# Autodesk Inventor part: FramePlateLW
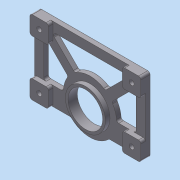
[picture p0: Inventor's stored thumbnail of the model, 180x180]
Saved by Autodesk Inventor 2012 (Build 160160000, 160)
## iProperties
Created: 2010-12
Part Number: FramePlateLW
Document SubType Name: Modeling
Designer: Alex
Density: 2.71 g/cm^3
Material: Aluminum-6061
Mass: 211.967 g
Surface Area: 316.378 cm^2
Volume: 78.2166 cm^3
Author: Alex
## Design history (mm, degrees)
sketch "Sketch1"
  geometry: L1 (-76.2, 76.2)-(76.2, 76.2); L2 (76.2, 76.2)-(76.2, -38.1); L3 (76.2, -38.1)-(-76.2, -38.1); L4 (-76.2, -38.1)-(-76.2, 76.2); C1 r 23.812 at (0, 0); C2 r 28.575 at (0, 0); 1 further point
  constraints: 8 end point, 2 centre point, 2 parallel, 1 horizontal, 1 perpendicular
  dimensions: "d0" = 114.3 distance between parallel lines of L3 L1; "d1" = 152.4 distance between parallel lines of L2 L4; "d2" = 76.2 distance from line of L1 point (0, 0); "d3" = 76.2 distance from line of L4 point (0, 0); "d49" = 47.625 diameter of C1; "d50" = 57.15 diameter of C2
extrude "Extrusion1" new body sketch "Sketch1" distance "d4" = 12.7; taper "d5" = 0 deg
sketch "Sketch2"
  geometry: 2 further points
hole "Hole1" sketch "Sketch2" at (0, 0) diameter "d7" = 47.6504; stored, may be unused: countersink angle "d11" = 82 deg, drill point angle "d13" = 118 deg; dims "d8" = 19.05, "d9" = 9.525, "d10" = 6.35, "d12" = 25.4
sketch "Sketch4"
  geometry: L1 (-76.2, 76.2)-(76.2, 76.2) reference; L2 (-76.2, -38.1)-(-76.2, 76.2) reference; 4 further points
  constraints: 1 horizontal, 1 vertical, 3 other
  dimensions: "d32" = 12.7 distance from line of point (-63.5, 63.5) L2; "d33" = 12.7 distance from line of L1 point (-63.5, 63.5); "d36" = 127 distance of point (-63.5, 63.5) point (63.5, 63.5); "d39" = 76.2 distance of point (-63.5, 63.5) point (-63.5, -12.7)
hole "Hole4" sketch "Sketch4" at (-63.5, 63.5), (63.5, 63.5), (-63.5, -12.7), (63.5, -12.7) diameter "d42" = 6.74688; stored, may be unused: countersink angle "d46" = 82 deg, drill point angle "d48" = 118 deg; dims "d43" = 19.05, "d44" = 9.525, "d45" = 6.35, "d47" = 25.4
sketch "Sketch7"
  geometry: L1 (-76.2, 76.2)-(76.2, 76.2) reference; L2 (-76.2, -38.1)-(-76.2, 76.2) reference; L3 (-63.5, 46.855)-(-63.5, 3.175); L4 (-31.733, 22.753)-(-58.08, 49.1); L5 (-63.5, 63.5)-(0, 0); L6 (63.5, 46.855)-(63.5, 3.175); L7 (46.855, 63.5)-(-46.855, 63.5); L8 (-60.325, 0)-(-39.56, 0); L9 (-49.1, 58.08)-(-22.753, 31.733); L10 (22.753, 31.733)-(49.1, 58.08); L11 (31.733, 22.753)-(58.08, 49.1); L12 (60.325, 0)-(39.56, 0); L13 (-73.025, 76.2)-(73.025, 76.2); L14 (76.2, 73.025)-(76.2, -22.225); L15 (-76.2, -22.225)-(-76.2, 73.025); L16 (73.025, -25.4)-(27.542, -25.4); L17 (-27.542, -25.4)-(-73.025, -25.4); L18 (-60.325, 0)-(-39.56, 0); L19 (39.56, 0)-(60.325, 0); L20 (76.2, 76.2)-(76.2, -38.1) reference; L21 (63.5, 63.5)-(0, 0); L22 (76.2, -38.1)-(-76.2, -38.1) reference; C1 r 23.825 at (0, 0) reference; C2 r 3.373 at (63.5, 63.5) reference; A1 r 3.175 centre (-46.855, 60.325) between (-46.855, 63.5) and (-49.1, 58.08); A2 r 3.175 centre (-60.325, 46.855) between (-58.08, 49.1) and (-63.5, 46.855); A3 r 3.175 centre (-60.325, 3.175) between (-63.5, 3.175) and (-60.325, 0); A4 r 3.175 centre (46.855, 60.325) between (49.1, 58.08) and (46.855, 63.5); A5 r 3.175 centre (60.325, 46.855) between (63.5, 46.855) and (58.08, 49.1); A6 r 3.175 centre (60.325, 3.175) between (60.325, 0) and (63.5, 3.175); A7 r 36.513 centre (0, 0) between (18.867, 31.26) and (-18.867, 31.26); A8 r 36.513 centre (0, 0) between (-31.26, 18.867) and (-36.395, 2.921); A9 r 36.513 centre (0, 0) between (36.395, 2.921) and (31.26, 18.867); A10 r 3.175 centre (-39.56, 3.175) between (-39.56, 0) and (-36.395, 2.921); A11 r 3.175 centre (-33.978, 20.508) between (-31.26, 18.867) and (-31.733, 22.753); A12 r 3.175 centre (-20.508, 33.978) between (-22.753, 31.733) and (-18.867, 31.26); A13 r 3.175 centre (20.508, 33.978) between (18.867, 31.26) and (22.753, 31.733); A14 r 3.175 centre (33.978, 20.508) between (31.733, 22.753) and (31.26, 18.867); A15 r 3.175 centre (39.56, 3.175) between (36.395, 2.921) and (39.56, 0); A16 r 36.513 centre (0, 0) between (-25.339, -26.289) and (25.339, -26.289); A17 r 3.175 centre (-27.542, -28.575) between (-25.339, -26.289) and (-27.542, -25.4); A18 r 3.175 centre (27.542, -28.575) between (27.542, -25.4) and (25.339, -26.289); A19 r 3.175 centre (-73.025, -22.225) between (-76.2, -22.225) and (-73.025, -25.4); A20 r 3.175 centre (-73.025, 73.025) between (-73.025, 76.2) and (-76.2, 73.025); A21 r 3.175 centre (73.025, 73.025) between (76.2, 73.025) and (73.025, 76.2); A22 r 3.175 centre (73.025, -22.225) between (73.025, -25.4) and (76.2, -22.225); 20 further points
  constraints: 52 point on circle, 36 end point, 36 tangent, 26 point on line, 22 centre point, 10 equal radius, 7 parallel, 4 collinear, 2 horizontal, 2 perpendicular, 1 coincident
  dimensions: "d66" = 12.7 distance between parallel lines of L2 L3; "d68" = 12.7 distance from line of L2 L5.start; "d71" = 45 deg angle of L5 L1; "d72" = 6.35 distance between parallel lines of L5 L4; "d79" = 12.7 distance between parallel lines of L1 L7; "d80" = 47.6504 diameter of C1 (derived); "d84" = 3.175 radius of A1; "d85" = 3.175 radius of A2; "d86" = 3.175 radius of A3; "d87" = 3.175 radius of A4; "d88" = 3.175 radius of A5; "d89" = 3.175 radius of A6; "d90" = 3.175 radius of A10; "d100" = 12.7 distance from line of L5.start L1; "d101" = 6.35 distance between parallel lines of L9 L5; "d103" = 36.5125 radius of A9; "d104" = 36.5125 radius of A8; "d107" = 36.5125 radius of A7; "d128" = 101.6 distance between parallel lines of L17 L1; "d129" = 36.5125 radius of A16; "d130" = 76.2 distance from line of point (0, 0) L1; "d131" = 76.2 distance from line of point (0, 0) L2; "d132" = 76.2 distance between parallel lines of L1 L8; "d133" = 12.7 distance between parallel lines of L6 L20; "d134" = 6.35 distance between parallel lines of L11 L21; "d135" = 6.35 distance between parallel lines of L10 L21; "d136" = 45 deg angle of L1 L21; "d137" = 26.2298 horizontal distance of point (0, 0) point (-26.23, -25.4); "d138" = 26.2298 horizontal distance of point (0, 0) point (26.23, -25.4); "d139" = 3.175 radius of A17; "d145" = 152.4 distance between parallel lines of L14 L2
extrude "Extrusion10" cut sketch "Sketch7" stored distance "d146" = 25.4; taper "d147" = 0 deg
sketch "Sketch10"
  geometry: L1 (31.733, 22.753)-(58.08, 49.1) reference; L2 (63.5, 46.855)-(63.5, 3.175) reference; L3 (60.325, 0)-(39.56, 0) reference; L4 (-39.56, 0)-(-60.325, 0) reference; L5 (-63.5, 3.175)-(-63.5, 46.855) reference; L6 (-58.08, 49.1)-(-31.733, 22.753) reference; L7 (-46.855, 63.5)-(46.855, 63.5) reference; L8 (49.1, 58.08)-(22.753, 31.733) reference; L9 (-22.753, 31.733)-(-49.1, 58.08) reference; L10 (-73.025, -25.4)-(-27.542, -25.4) reference; L11 (27.542, -25.4)-(73.025, -25.4) reference; L12 (76.2, 73.025)-(76.2, -22.225) reference; L13 (-73.025, 76.2)-(73.025, 76.2) reference; L14 (-76.2, -22.225)-(-76.2, 73.025) reference; L15 (-73.025, 76.2)-(-53.975, 76.2); L16 (-50.8, 73.025)-(-50.8, 53.987); L17 (-53.975, 50.812)-(-73.025, 50.812); L18 (-76.2, 53.987)-(-76.2, 73.025); L19 (73.025, 76.2)-(53.975, 76.2); L20 (50.8, 73.025)-(50.8, 53.987); L21 (53.975, 50.812)-(73.025, 50.812); L22 (76.2, 53.987)-(76.2, 73.025); L23 (73.025, -25.4)-(53.975, -25.4); L24 (50.8, -22.225)-(50.8, -3.175); L25 (53.975, 0)-(73.025, 0); L26 (76.2, -3.175)-(76.2, -22.225); L27 (-73.025, -25.4)-(-53.975, -25.4); L28 (-50.8, -22.225)-(-50.8, -3.175); L29 (-53.975, 0)-(-73.025, 0); L30 (-76.2, -3.175)-(-76.2, -22.225); L31 (76.2, 73.025)-(76.2, -22.225) reference; C1 r 27.483 at (0, 0); A1 r 3.175 centre (60.325, 46.855) between (63.5, 46.855) and (58.08, 49.1) reference; A2 r 3.175 centre (60.325, 3.175) between (60.325, 0) and (63.5, 3.175) reference; A3 r 3.175 centre (39.56, 3.175) between (36.395, 2.921) and (39.56, 0) reference; A4 r 36.512 centre (0, 0) between (36.395, 2.921) and (31.26, 18.867) reference; A5 r 3.175 centre (33.978, 20.508) between (31.733, 22.753) and (31.26, 18.867) reference; A6 r 3.175 centre (-39.56, 3.175) between (-39.56, 0) and (-36.395, 2.921) reference; A7 r 3.175 centre (-60.325, 3.175) between (-63.5, 3.175) and (-60.325, 0) reference; A8 r 3.175 centre (-60.325, 46.855) between (-58.08, 49.1) and (-63.5, 46.855) reference; A9 r 3.175 centre (-33.978, 20.508) between (-31.26, 18.867) and (-31.733, 22.753) reference; A10 r 36.513 centre (0, 0) between (-31.26, 18.867) and (-36.395, 2.921) reference; A11 r 3.175 centre (-46.855, 60.325) between (-46.855, 63.5) and (-49.1, 58.08) reference; A12 r 3.175 centre (46.855, 60.325) between (49.1, 58.08) and (46.855, 63.5) reference; A13 r 3.175 centre (20.508, 33.978) between (18.867, 31.26) and (22.753, 31.733) reference; A14 r 36.513 centre (0, 0) between (18.867, 31.26) and (-18.867, 31.26) reference; A15 r 3.175 centre (-20.508, 33.978) between (-22.753, 31.733) and (-18.867, 31.26) reference; A16 r 3.175 centre (-73.025, -22.225) between (-76.2, -22.225) and (-73.025, -25.4) reference; A17 r 3.175 centre (-27.542, -28.575) between (-25.339, -26.289) and (-27.542, -25.4) reference; A18 r 36.513 centre (0, 0) between (-25.339, -26.289) and (25.339, -26.289) reference; A19 r 3.175 centre (27.542, -28.575) between (27.542, -25.4) and (25.339, -26.289) reference; A20 r 3.175 centre (73.025, -22.225) between (73.025, -25.4) and (76.2, -22.225) reference; A21 r 3.175 centre (73.025, 73.025) between (76.2, 73.025) and (73.025, 76.2) reference; A22 r 3.175 centre (-73.025, 73.025) between (-73.025, 76.2) and (-76.2, 73.025) reference; A23 r 3.175 centre (-73.025, 73.025) between (-73.025, 76.2) and (-76.2, 73.025); A24 r 3.175 centre (-53.975, 53.987) between (-53.975, 50.812) and (-50.8, 53.987); A25 r 3.175 centre (-53.975, 73.025) between (-50.8, 73.025) and (-53.975, 76.2); A26 r 3.175 centre (-73.025, 53.987) between (-76.2, 53.987) and (-73.025, 50.812); A27 r 3.175 centre (53.975, 53.987) between (50.8, 53.987) and (53.975, 50.812); A28 r 3.175 centre (53.975, 73.025) between (53.975, 76.2) and (50.8, 73.025); A29 r 3.175 centre (73.025, 73.025) between (76.2, 73.025) and (73.025, 76.2); A30 r 3.175 centre (73.025, 53.987) between (73.025, 50.812) and (76.2, 53.987); A31 r 3.175 centre (73.025, -3.175) between (76.2, -3.175) and (73.025, 0); A32 r 3.175 centre (73.025, -22.225) between (73.025, -25.4) and (76.2, -22.225); A33 r 3.175 centre (53.975, -22.225) between (50.8, -22.225) and (53.975, -25.4); A34 r 3.175 centre (53.975, -3.175) between (53.975, 0) and (50.8, -3.175); A35 r 3.175 centre (-53.975, -3.175) between (-50.8, -3.175) and (-53.975, 0); A36 r 3.175 centre (-53.975, -22.225) between (-53.975, -25.4) and (-50.8, -22.225); A37 r 3.175 centre (-73.025, -22.225) between (-76.2, -22.225) and (-73.025, -25.4); A38 r 3.175 centre (-73.025, -3.175) between (-73.025, 0) and (-76.2, -3.175); 4 further points
  constraints: 32 end point, 32 point on circle, 32 tangent, 17 centre point, 15 equal radius, 12 point on line, 9 collinear, 8 parallel, 4 horizontal, 4 perpendicular, 1 coincident
  dimensions: "d148" = 25.4 distance between parallel lines of L16 L14; "d149" = 25.38762 distance between parallel lines of L13 L17; "d150" = 25.4 distance between parallel lines of L12 L20; "d151" = 3.175 radius of A23; "d154" = 54.9656 diameter of C1
extrude "Extrusion12" cut sketch "Sketch10" distance "d155" = 6.35; taper "d156" = 0 deg
sketch "Sketch11"
  geometry: C1 r 3.373 at (-63.5, -12.7) reference; C2 r 3.373 at (63.5, -12.7) reference; C3 r 3.373 at (-63.5, 63.5) reference; C4 r 3.373 at (63.5, 63.5) reference; C5 r 6.35 at (-63.5, 63.5); C6 r 6.35 at (63.5, 63.5); C7 r 6.35 at (-63.5, -12.7); C8 r 6.35 at (63.5, -12.7)
  constraints: 4 centre point, 4 coincident, 3 equal radius
  dimensions: "d157" = 12.7 diameter of C5
extrude "Extrusion13" cut sketch "Sketch11" distance "d158" = 6.35; taper "d159" = 0 deg
body "Solid1"
other parameters: "d74" = 6.35, "d77" = 6.35, "d81" = 73.025, "d93" = 73.025, "d105" = 0, "sa_0" = 0, "sa_1" = 0, "sa_2" = 177928.88
